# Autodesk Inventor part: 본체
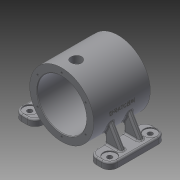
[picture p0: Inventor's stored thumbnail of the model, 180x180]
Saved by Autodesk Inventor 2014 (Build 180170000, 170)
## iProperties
Created: 2024-02
Part Number: 본체
Material: 알루미늄 6061
Document SubType Name: Modeling
Designer: mdu-01
Density: 2.71 g/cm^3
Appearance: 기본값
Author: mdu-01
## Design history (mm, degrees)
sketch "스케치1"
  geometry: C1 r 12 at (0, 11) reference; C2 r 60 at (0, 11); C3 r 46 at (0, 11); C4 r 14 at (0, -20) reference; A1 r 16 centre (0, -20) between (-3.969, -4.5) and (3.969, -4.5) reference; 1 further point
  constraints: 2 centre point, 2 coincident
  dimensions: "d0" = 120 diameter of C2; "d1" = 14 radial gap between concentric circles of C2 C3
extrude "돌출1" new body sketch "스케치1" distance "d2" = 106; taper "d3" = 0 deg
sketch "스케치2"
  geometry: L1 (58, 89)-(67, 89) reference; L2 (71, 0)-(71, 106) reference; L3 (53, 94)-(53, 64) reference; L4 (53, 79)-(71, 79); L5 (67, 89)-(71, 89); L6 (53, 94)-(58, 94); L7 (58, 94)-(58, 89); L8 (53, 79)-(43, 79); L9 (43, 79)-(43, 94); L10 (43, 94)-(53, 94); 1 further point
  constraints: 16 end point, 4 perpendicular, 2 parallel, 2 point on line, 1 horizontal, 1 midpoint, 1 vertical, 2 other
  dimensions: "d5" = 10 distance between parallel lines of L9 L3
revolve "회전1" sketch "스케치2" stored, may be unused: angle "d4" = 90 deg
sketch "스케치3"
  geometry: C1 r 60 at (0, 0) reference; 2 further points
  constraints: 2 vertical alignment, 2 other
  dimensions: "d6" = 8 dimension on C1
hole "구멍1" sketch "스케치3" at (0, 52) diameter "d7" = 3.242; stored, may be unused: countersink angle "d11" = 90 deg, drill point angle "d13" = 118 deg; dims "d8" = 8, "d9" = 8, "d10" = 4.6, "d12" = 10
hole "구멍2" diameter "d16" = 3.242; stored, may be unused: countersink angle "d20" = 90 deg, drill point angle "d22" = 118 deg; dims "d14" = 10, "d15" = 10, "d17" = 8, "d18" = 8, "d19" = 4.6, "d21" = 10
sketch "스케치4"
  geometry: L1 (50, -54)-(90, -54); L2 (90, -54)-(90, -42); L3 (90, -42)-(50, -42); L4 (50, -42)-(50, -54); C1 r 60 at (0, 11) reference; 1 further point
  constraints: 8 end point, 2 parallel, 1 horizontal, 1 perpendicular
  dimensions: "d26" = 12 distance between parallel lines of L1 L3; "d28" = 65 distance from line of L1 C1.centre; "d29" = 50 distance from line of L4 C1.centre; "d30" = 40 distance between parallel lines of L2 L4
extrude "돌출2" join sketch "스케치4" distance "d31" = 106; taper "d32" = 0 deg
node "작업 평면1"
sketch "스케치5"
  geometry: L1 (-90, -42)-(-50, -42) reference; L2 (-50, -42)-(-50, -22.166); L3 (-80, -42)-(-58.084, -4.041); A1 r 60 centre (0, 11) between (-50, -22.166) and (-58.084, -4.041) reference; 1 further point
  constraints: 4 end point, 2 point on circle, 1 perpendicular, 1 point on line
  dimensions: "d33" = 10 distance of L3.start L1.start; "d34" = 60 deg angle of L1 L3
extrude "돌출3" join sketch "스케치5" distance "d37" = 9; taper "d38" = 0 deg
node "작업 평면3"
fillet "모깎기1" dims "d39" = 15
sketch "스케치6"
  geometry: A1 r 15 centre (25, 16) between (40, 16) and (25, 31) reference; A2 r 15 centre (25, -60) between (25, -75) and (40, -60) reference; 1 further point
hole "구멍3" sketch "스케치6" at (25, -60), (25, 16) diameter "d40" = 9; stored, may be unused: countersink angle "d44" = 90 deg, drill point angle "d46" = 118 deg; dims "d41" = 8, "d42" = 24, "d43" = 2, "d45" = 10
fillet "모깎기2" dims "d47" = 3
fillet "모깎기3" dims "d48" = 3
fillet "모깎기4" dims "d49" = 3
fillet "모깎기5" dims "d50" = 3
sketch "스케치7"
  geometry: L1 (71, 106)-(-49, 106) reference; 3 further points
  constraints: 1 midpoint, 1 vertical alignment, 1 other
  dimensions: "d51" = 53 distance from line of point (11, 53) L1
feature "엠보싱1" sketch "스케치7" dims "d0" = 120, "d1" = 14, "d52" = 0.5, "d53" = 0
chamfer "모따기1" distance "d54" = 1; stored, may be unused: second distance "d55" = 2, angle "d56" = 45 deg
node "솔리드1"
pattern_circular "원형 패턴1" dims angle "d24" = 360 deg
mirror "대칭1"
mirror "대칭2"
node "참조1"
node "참조2"
node "참조3"
node "참조4"
